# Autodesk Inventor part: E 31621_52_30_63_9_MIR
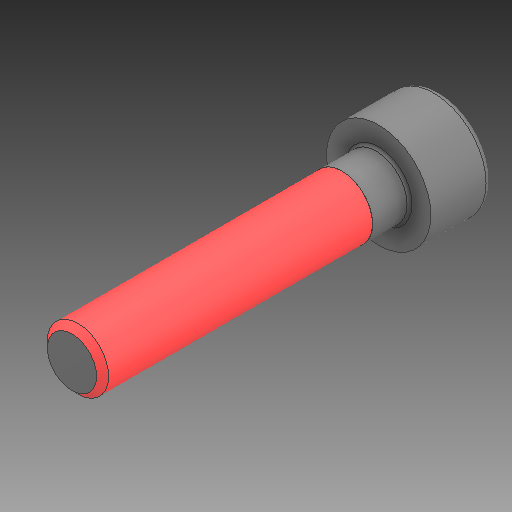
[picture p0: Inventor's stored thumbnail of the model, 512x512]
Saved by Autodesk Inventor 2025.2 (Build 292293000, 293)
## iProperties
Created: 2025-03
Part Number: E 31621_52_30_63_9_MIR
Material: Všeobecné
Document SubType Name: Modeling
Designer: Patrik
Stock Number: E 31621_52_30_63
Mass: 0.73741 g
Surface Area: 6.62537 cm^2
Volume: 0.73741 cm^3
Density: 1 g/cm^3
Appearance: Výchozí
Author: Patrik
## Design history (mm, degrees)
derived "E 31621_52_30_63_9.ipt"
feature "Těleso1::E 31621_52_30_63_9.ipt" dims "d0" = 10
tag "Prvek štítků1"
node "Těleso1"
